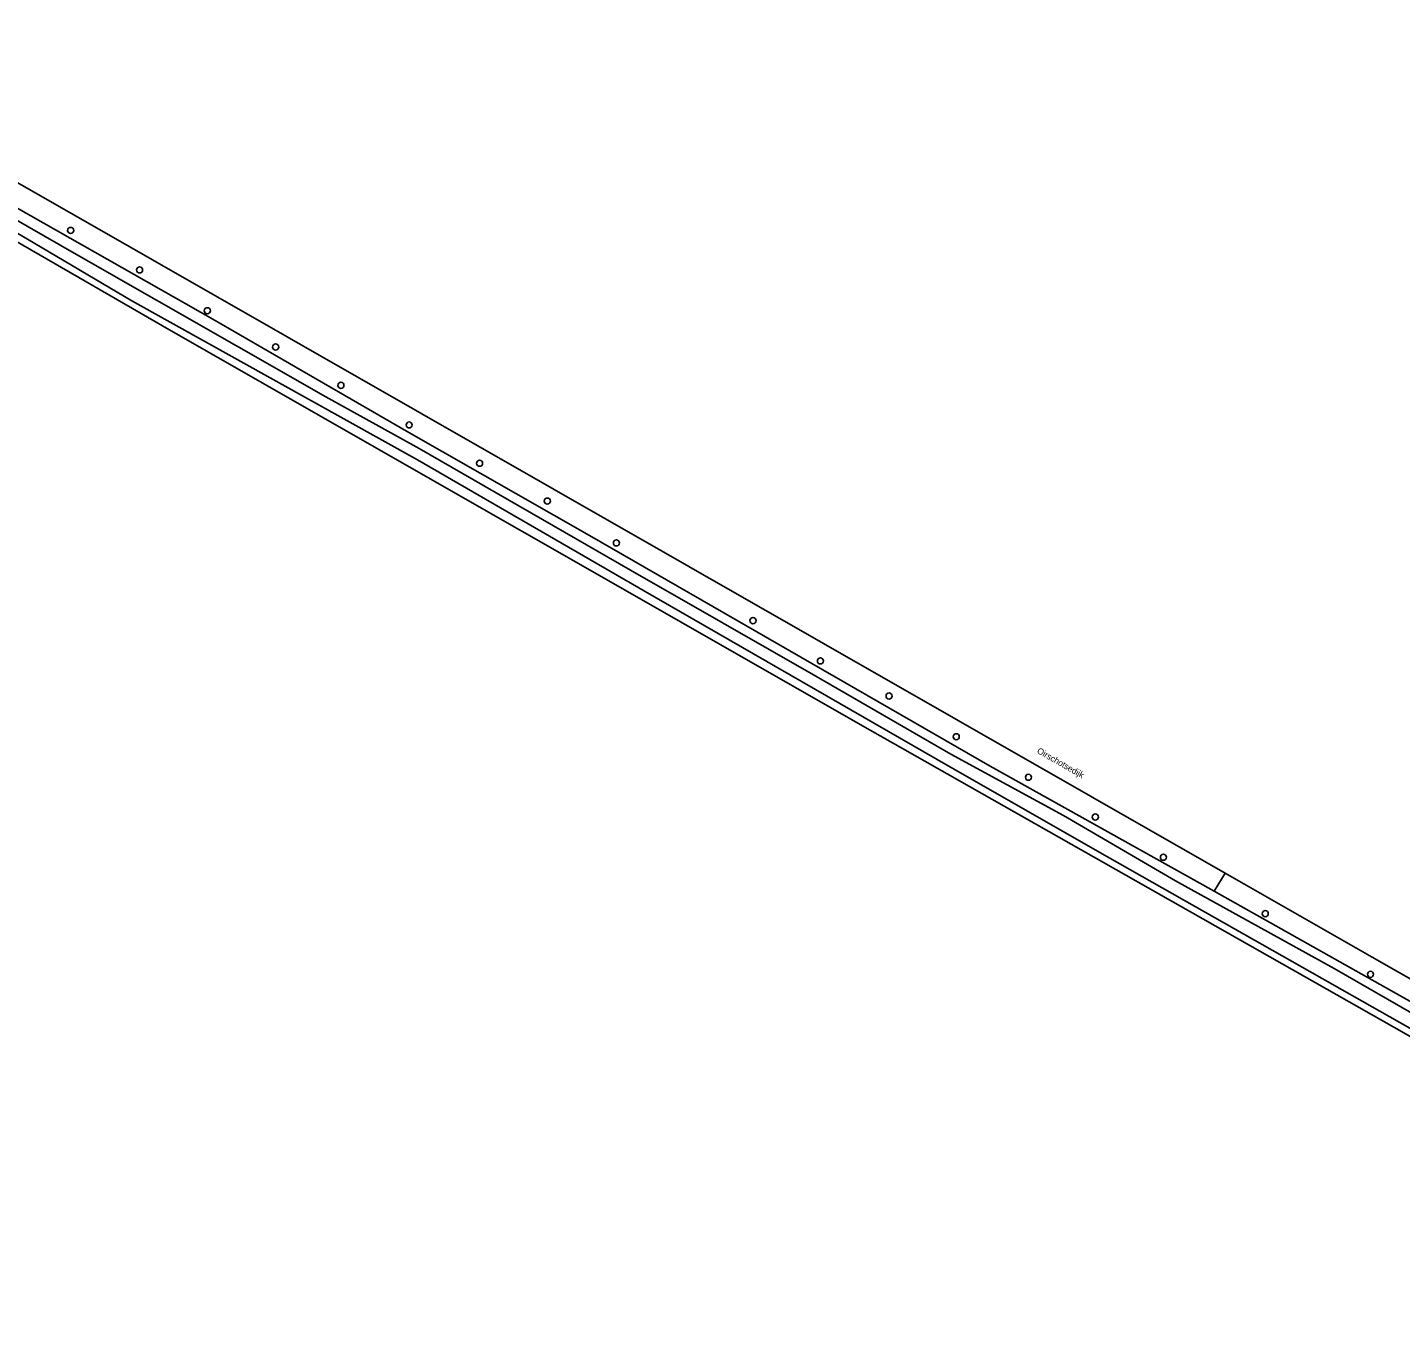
# Model space of a CAD drawing. Extents: x 156502 to 159074, y 384229 to 386094.
# Drawn here: x 158639.1 to 158859.3, y 385057.2 to 385264.8 of the extents above; entities that cross this region are included whole.
import ezdxf

# ---------------------------------------------------------------- set-up
doc = ezdxf.new("R2010")
doc.units = 0
for name, color, linetype in [('IMGEO_Boom', 7, 'Continuous'), ('IMGEO_Gemengd_bos', 7, 'Continuous'), ('IMGEO_Groenvoorziening', 7, 'Continuous'), ('IMGEO_Openbare_ruimte_label', 7, 'Continuous'), ('IMGEO_Rijbaan_lokaal_gesloten', 7, 'Continuous'), ('IMGEO_Waterloop', 7, 'Continuous')]:
    doc.layers.add(name, color=color, linetype=linetype)

msp = doc.modelspace()

# ---------------------------------------------------------------- linework, layer by layer
at = {"layer": 'IMGEO_Boom'}
for centre in [(158646.01, 385232.26), (158657.06, 385225.93), (158667.93, 385219.38), (158678.89, 385213.56), (158689.36, 385207.41), (158700.31, 385201.06), (158711.6, 385194.91), (158722.47, 385188.84), (158733.55, 385182.14), (158755.46, 385169.66), (158766.28, 385163.21), (158777.29, 385157.57), (158788.06, 385151.04), (158799.65, 385144.54), (158810.37, 385138.16), (158821.3, 385131.71), (158837.63, 385122.65), (158854.51, 385112.93)]:
    msp.add_circle(centre, 0.489, dxfattribs=at)
at = {"layer": 'IMGEO_Gemengd_bos'}
msp.add_lwpolyline([(158587.52, 385259.81), (158603.48, 385250), (158662.11, 385216.13), (158774.28, 385152.08), (158859.86, 385103.52), (158940.81, 385057.23), (158941.64, 385057.92), (158942.32, 385058.77)], dxfattribs=at)
at = {"layer": 'IMGEO_Groenvoorziening'}
for points in [[(158829.41, 385126.26), (158793.5, 385146.3), (158729.24, 385183.31), (158699.87, 385200.04), (158668.84, 385218.02), (158628.95, 385240.64), (158609.63, 385252.21), (158598.88, 385258.58), (158593.18, 385261.26), (158590.67, 385261.86), (158589.3, 385261.89)], [(158831.21, 385129.16), (158829.41, 385126.26)], [(158829.41, 385126.26), (158913.09, 385079.19), (158942.62, 385062.12), (158943.1, 385060.85), (158942.82, 385059.77), (158942.32, 385058.77)]]:
    msp.add_lwpolyline(points, dxfattribs=at)
at = {"layer": 'IMGEO_Rijbaan_lokaal_gesloten'}
for points in [[(158593.54, 385264.82), (158594.64, 385264.37), (158831.21, 385129.16)], [(158831.21, 385129.16), (158854.77, 385115.68), (158942.61, 385065.61)]]:
    msp.add_lwpolyline(points, dxfattribs=at)
at = {"layer": 'IMGEO_Waterloop'}
for points in [[(158616.11, 385244.35), (158639.09, 385230.84), (158655.82, 385220.95), (158701.63, 385195.46), (158738.15, 385174.34), (158786.76, 385146.35), (158812.7, 385131.58), (158827.9, 385122.97), (158864.02, 385102.45), (158881.59, 385092.31), (158929.52, 385064.8), (158939.86, 385059.04)], [(158939.86, 385059.04), (158940.34, 385059), (158940.77, 385059.15), (158941.25, 385059.57), (158941.5, 385060.1), (158941.6, 385060.57), (158941.53, 385061.08), (158941.3, 385061.41), (158908.63, 385079.24), (158898.14, 385085.51), (158873.98, 385099.3), (158848.67, 385113.84), (158840.55, 385118.37), (158823.23, 385127.94), (158805.24, 385138.42), (158787.22, 385148.24), (158765.55, 385160.78), (158735.79, 385177.77), (158701.94, 385197.26), (158686.94, 385205.57), (158672.6, 385213.76), (158647.3, 385228.18), (158619.92, 385243.9)]]:
    msp.add_lwpolyline(points, dxfattribs=at)

# ---------------------------------------------------------------- texts
at = {"layer": 'IMGEO_Openbare_ruimte_label'}
msp.add_text('Oirschotsedijk', height=1, rotation=330.4114, dxfattribs=at).set_placement((158800.91, 385148.49))

doc.saveas('drawing.dxf')
